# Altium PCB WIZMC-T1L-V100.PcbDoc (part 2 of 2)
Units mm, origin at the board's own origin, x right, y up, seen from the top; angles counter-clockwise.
Board outline 48.5 x 42.5 mm, 4 copper layers (Top Layer, GND, POWER, Bottom Layer), stack 0.603 mm thick; 133 components, 92 nets, 478 pads, 203 vias.
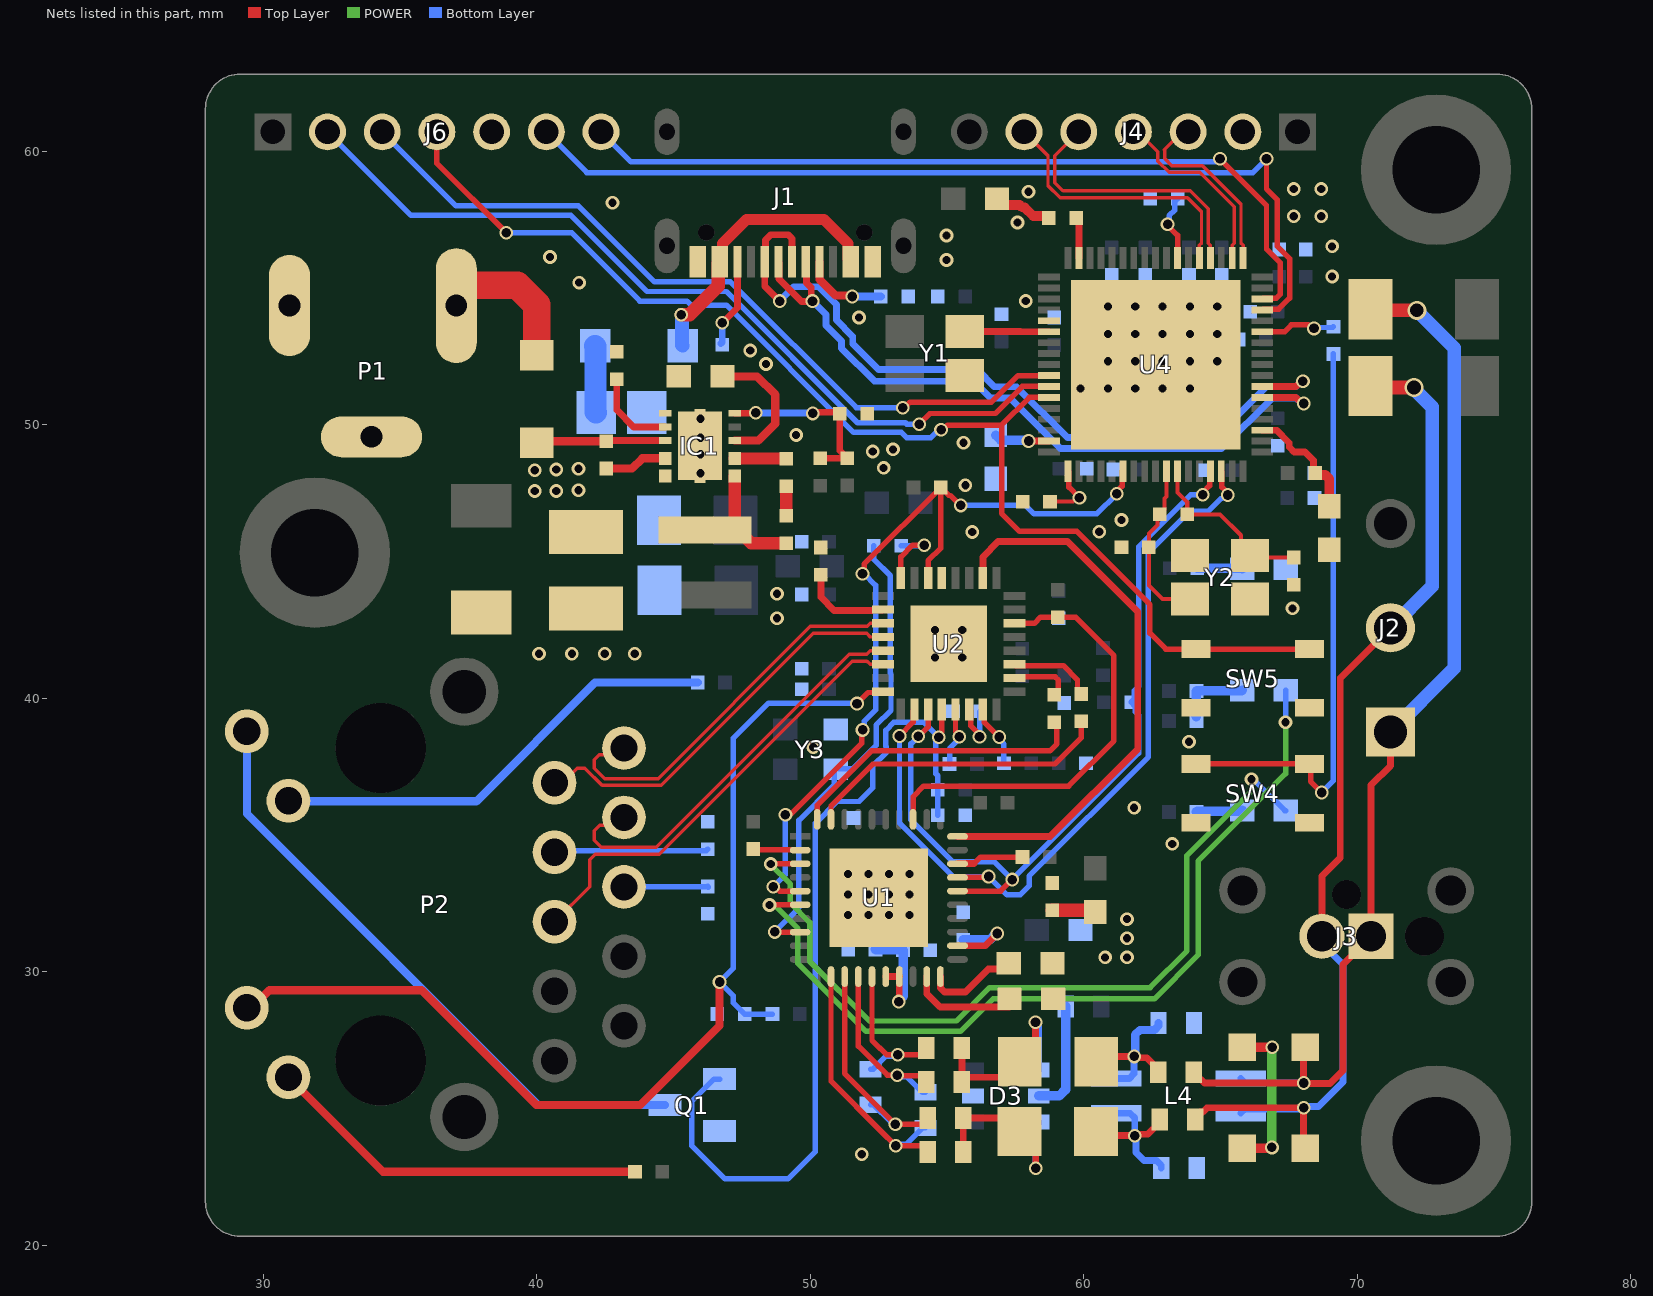
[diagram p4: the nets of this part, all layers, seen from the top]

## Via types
v1: diameter 0.5, hole 0.3, Top Layer to Bottom Layer, tented both sides, 116 vias
v2: diameter 0.5, hole 0.35, Top Layer to Bottom Layer, tented both sides, 81 vias
v3: diameter 0.6, hole 0.3, Top Layer to Bottom Layer, tented both sides, 4 vias
v4: diameter 0.7, hole 0.5, Top Layer to Bottom Layer, tented both sides, 2 vias

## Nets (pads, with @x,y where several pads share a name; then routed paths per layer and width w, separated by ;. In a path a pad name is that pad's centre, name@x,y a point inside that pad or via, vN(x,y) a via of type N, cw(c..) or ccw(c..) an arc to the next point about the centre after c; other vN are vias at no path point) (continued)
GND: C3.1 C4.1 C5.1 C6.1 C7.1 C8.1 C9.1 C10.1 C11.1 C12.1 C14.1 C15.1 C16.1 C17.1 C19.1 C20.2 C21.2 C22.1 C25.1 C29.1 C30.1 C31.1 C33.1 C34.1 C35.1 C36.1 C37.1 C38.1 C39.1 C40.1 C41.1 C43.2 C44.2 C45.1 C46.1 C47.1 C48.1 C49.1 C50.1 C51.1 C52.1 C53.1 C54.1 C55.1 C56.1 C57.1 D3.2 IC1.6 IC1.10 IC1.11 IC1.A11 IC1.B11 J1.A1_B12 J1.B1_A12 J4.2 J6.5 LD3.2 P1.2 P1.3 Q1.2 R3.1 R5.1 R10.2 R15.2 R16.1 R24.1 R33.1 R52.1 R53.1 R54.2 SW4.1 SW4.2 SW5.1 SW5.2 U1.41 U2.5 U2.33 U4.22 U4.69 Y1.2 Y2.2 Y2.4 Y3.2
  other v1: 51.877,23.32 51.377,32.07 52.127,32.07 52.877,32.07 53.627,32.07 51.377,32.82 52.127,32.82 52.877,32.82 53.627,32.82 51.377,33.57 52.127,33.57 52.877,33.57 53.627,33.57 63.234,34.671 61.837,35.992 50.102,38.202 63.843,38.405 40.077,41.62 41.277,41.62 42.477,41.62 43.577,41.62 48.777,42.92 67.628,43.282 48.777,43.82 55.917,46.076 60.558,46.086 61.372,46.513 55.667,47.783 45.977,48.22 52.677,48.42 45.977,48.92 52.277,49.02 53.018,49.096 55.599,49.34 45.977,49.52 49.477,49.62 45.977,50.22 59.877,51.32 60.877,51.32 61.877,51.32 62.877,51.32 63.877,51.32 48.373,52.216 60.877,52.32 61.877,52.32 62.877,52.32 63.877,52.32 64.877,52.32 47.8,52.714 60.877,53.32 61.877,53.32 62.877,53.32 63.877,53.32 64.877,53.32 51.777,53.92 60.877,54.32 61.877,54.32 62.877,54.32 63.877,54.32 64.877,54.32 57.877,54.52 41.542,55.194 69.077,55.42 54.977,56.02 40.475,56.134 69.077,56.52 54.977,56.92 57.569,57.396 67.677,57.62 68.677,57.62 42.761,58.115 57.977,58.52 67.677,58.62 68.677,58.62
  other v3: 54.555,41.486 55.555,41.486 54.555,42.486 55.555,42.486
LED0: P2.L2 R50.1 R53.2 U2.16 | length 40
  Top Layer w0.2: v2(51.702,39.802) 52.106,40.206 52.622,40.206 U2.16@52.652,40.236
  Top Layer w0.3: P2.L2@29.392,28.676 29.574,28.676 30.218,29.32 35.777,29.32 39.977,25.12 43.777,25.12 46.677,28.02 v2(46.677,29.62)
  Bottom Layer w0.2: R50.1@48.611,28.448 R53.2@47.597,28.448 47.177,28.868 47.177,29.12 v2(46.677,29.62) 47.177,30.12 47.177,38.528 48.469,39.82 51.684,39.82 v2(51.702,39.802)
LINK_ST: Q1.1 R49.1 R52.2 U2.20 | length 31.4
  Top Layer w0.2: v2@54.805,38.774 U2.20@54.805,39.584
  Bottom Layer w0.2: Q1.1@46.677,26.07 46.477,26.07 45.66,25.253 45.66,23.637 46.877,22.42 49.177,22.42 50.177,23.42 50.177,35.42 50.977,36.22 51.777,36.22 52.277,36.72 52.277,37.52 52.777,38.02 52.777,38.22 52.756,38.241 52.756,38.822 53.054,39.12 54.142,39.12 v2(54.687,38.575) 54.687,38.493 54.588,38.395 54.588,37.238 54.656,37.17 R49.1@54.656,36.652 R52.2@54.656,35.712
MDC: U1.27 U2.18 U4.49 | length 30.2
  Top Layer w0.2: v2(53.256,38.615) 53.256,38.622 53.755,39.121 53.755,39.534 U2.18@53.805,39.584 ; U1.27@55.377,33.444 55.385,33.452 56.488,33.452 v2(56.513,33.478) ; U4.49@65.024,48.297 65.049,48.272 65.049,47.72 65.259,47.51 v2(65.259,47.429)
  Bottom Layer w0.2: v2(53.256,38.615) 53.258,38.613 53.258,35.427 55.207,33.478 v2(56.513,33.478) 57.188,32.803 57.668,32.803 57.996,33.13 57.996,33.489 62.354,37.848 62.354,45.323 63.874,46.843 64.553,46.843 65.01,47.3 65.049,47.3 65.178,47.429 v2(65.259,47.429)
MDI_0_N: P2.R2 U2.12 | length 14.9
  Top Layer w0.125: P2.R2@40.642,36.906 40.932,36.906 41.466,37.44 41.747,37.44 42.378,36.809 44.541,36.809 50.104,42.371 52.052,42.371 52.187,42.236 U2.12@52.652,42.236
MDI_0_P: P2.R1 U2.11 | length 14.6
  Top Layer w0.125: P2.R1@43.182,38.176 42.928,37.922 42.279,37.922 42.101,37.744 42.101,37.44 42.482,37.059 44.438,37.059 50,42.621 52.072,42.621 52.187,42.736 U2.11@52.652,42.736
MDI_1_N: P2.R6 U2.14 | length 16.6
  Top Layer w0.125: P2.R6@40.642,31.826 41.923,33.107 41.923,34.087 42.13,34.294 44.465,34.294 51.526,41.355 52.068,41.355 52.187,41.236 U2.14@52.652,41.236
MDI_1_P: P2.R3 U2.13 | length 15.3
  Top Layer w0.125: P2.R3@43.182,35.636 42.9,35.354 42.301,35.354 42.101,35.154 42.101,34.798 42.355,34.544 44.361,34.544 51.423,41.605 52.056,41.605 52.187,41.736 U2.13@52.652,41.736
MDIO: R12.1 U1.26 U2.19 U4.48 | length 29.5
  Top Layer w0.2: v2(53.945,38.604) 53.959,38.604 54.305,38.95 U2.19@54.305,39.584 ; U1.26@55.377,32.944 56.956,32.944 v2(57.377,33.365) ; v2(64.351,47.438) 64.351,47.519 64.599,47.768 64.599,48.272 U4.48@64.624,48.297
  Bottom Layer w0.2: v2(53.945,38.604) 53.671,38.33 53.671,35.546 55.207,34.011 56.731,34.011 v2(57.377,33.365) 62.004,37.993 62.004,39.376 61.877,39.503 61.877,39.703 R12.1@61.727,39.853 61.841,39.966 61.841,40.263 62.004,40.427 62.004,45.532 63.91,47.438 v2(64.351,47.438)
MDIX_MODE: R46.1 U2.21 | length 2.2
  Top Layer w0.2: U2.21@55.305,39.584 55.305,38.796 55.437,38.664 v2(55.437,38.583)
  Bottom Layer w0.2: R46.1@55.088,37.592 55.088,38.153 55.437,38.502 v2(55.437,38.583)
MEDIA_CNV: R40.1 U1.2 | length 1.7
  Top Layer w0.2: R40.1@47.904,34.48 47.932,34.452 49.618,34.452 U1.2@49.626,34.444
NetC1_1: C1.1 R1.1 | length 1.1
  Top Layer w0.45: R1.1@49.116,46.668 C1.1@49.116,47.751
NetC1_2: C1.2 IC1.2 | length 1.9
  Top Layer w0.45: IC1.2@47.237,48.769 47.237,48.76 49.107,48.76 C1.2@49.116,48.751
NetC2_1: C2.1 IC1.5 R4.1 R5.2 | length 6.7
  Top Layer w0.25: IC1.5@47.237,50.419 47.983,50.419 v2(47.999,50.435) ; v2(50.081,50.41) 50.124,50.452 51.03,50.452 51.072,50.494 51.072,49.054 R4.1@51.35,48.776 51.346,48.772 50.363,48.772 C2.1@50.359,48.768
  Bottom Layer w0.25: v2(47.999,50.435) 48.011,50.423 50.069,50.423 v2(50.081,50.41)
NetC18_1: C18.1 D3.4 R7.2 R9.2 | length 7.1
  Top Layer w0.25: R7.2@55.539,27.208 R9.2@55.539,25.963 55.713,26.137 57.092,26.137 C18.1@57.655,26.7 58.23,27.275 v2(58.23,28.143)
  Bottom Layer w0.25: v2(58.23,28.143) 58.23,28.076 58.35,27.955 D3.4@58.35,26.405
NetC18_2: C18.2 L4.2 R8.2 R10.1 | length 5.9
  Top Layer w0.25: C18.2@60.455,26.7 60.654,26.899 v2(61.837,26.899) 61.884,26.851 62.291,26.851 62.723,26.419 R8.2@62.723,26.319
  Bottom Layer w0.25: L4.2@61.185,26.09 61.662,26.09 61.837,26.265 v2(61.837,26.899)
  Bottom Layer w0.3: v2(61.837,26.899) 61.875,26.937 61.875,27.694 62.051,27.87 62.577,27.87 62.727,28.02 R10.1@62.727,28.12
NetC22_2: C22.2 IC1.3 | length 5
  Top Layer w0.3: C22.2@46.787,51.765 48.047,51.765 48.716,51.096 48.716,50.035 48.1,49.419 IC1.3@47.237,49.419
NetC23_2: C23.2 D4.1 J2.2 J3.2 L4.4 R36.1 | length 39.1
  Top Layer w0.25: R36.1@64.074,24.592 64.074,24.692 64.249,24.867 64.349,24.867 64.501,25.019 v2(68.034,25.019) 68.034,23.604 D4.1@68.092,23.546 ; J3.2@68.704,31.293 68.704,33.493 69.377,34.166 69.377,40.738 J2.2@71.209,42.57
  Top Layer w0.5: C23.2@70.478,51.41 70.529,51.359 v4(72.073,51.359)
  Bottom Layer w0.25: L4.4@65.735,24.82 65.886,24.971 v2@67.986,24.971 ; v2(68.034,25.019) 68.082,25.067 68.575,25.067 69.472,25.964 69.472,30.254 68.704,31.021 J3.2@68.704,31.293
  Bottom Layer w0.5: J2.2@71.209,42.57 72.733,44.094 72.733,50.644 72.073,51.305 v4(72.073,51.359)
NetC24_2: C24.2 D2.2 J2.1 J3.1 L4.3 R8.1 | length 41.3
  Top Layer w0.25: R8.1@64.023,26.319 64.023,26.219 64.198,26.044 64.298,26.044 64.415,25.926 v2(68.038,25.926) ; D2.2@68.092,27.229 68.034,27.171 68.034,25.93 v2(68.038,25.926) ; J2.1@71.209,38.76 71.209,37.525 70.504,36.82 J3.1@70.504,31.293 69.472,30.261 69.472,26.38 68.999,25.908 68.056,25.908 v2(68.038,25.926)
  Top Layer w0.5: C24.2@70.478,54.218 70.519,54.178 v4(72.174,54.178)
  Bottom Layer w0.25: L4.3@65.735,26.09 65.892,25.933 68.031,25.933 v2(68.038,25.926)
  Bottom Layer w0.5: J2.1@71.209,38.76 73.546,41.097 73.546,52.807 v4(72.174,54.178)
NetC25_2: C25.2 R13.1 U4.54 | length 4.5
  Top Layer w0.25: U4.54@66.524,49.797 67.038,49.797 67.509,49.326 67.509,49.183 67.691,49.002 68.087,49.002 68.391,48.698 68.391,48.302 R13.1@68.458,48.235
  Top Layer w0.35: R13.1@68.458,48.235 68.533,48.16 68.832,48.16 68.977,48.015 C25.2@68.977,47.02
NetC33_2: C33.2 U4.35 | length 2.3
  Top Layer w0.15: C33.2@58.763,47.187 59.604,47.187 59.743,47.326 v2(59.837,47.326)
  Top Layer w0.2: U4.35@59.424,48.297 59.449,48.272 59.449,47.715 59.837,47.327 v2(59.837,47.326)
NetC38_2: C38.2 U4.33 | length 2
  Top Layer w0.2: U4.33@58.721,49.4 U4.33@58.724,49.397
  Top Layer w0.25: v2(57.976,49.403) 57.979,49.4 U4.33@58.721,49.4
  Bottom Layer w0.35: C38.2@56.777,49.62 56.965,49.432 57.947,49.432 v2(57.976,49.403)
NetC42_1: C42.1 D3.6 R35.2 R37.2 | length 6.8
  Top Layer w0.25: R37.2@55.59,23.398 R35.2@55.59,24.642 57.156,24.642 58.238,23.56 v2(58.238,22.811)
  Bottom Layer w0.25: v2(58.238,22.811) 58.238,24.393 D3.6@58.35,24.505
NetC42_2: C42.2 L4.1 R33.2 R36.2 | length 5.9
  Top Layer w0.25: C42.2@60.443,24.155 60.595,24.003 v2(61.862,24.003) 61.91,24.051 62.333,24.051 62.774,24.492 R36.2@62.774,24.592
  Bottom Layer w0.25: L4.1@61.185,24.82 61.687,24.82 61.862,24.645 v2(61.862,24.003) 61.91,23.955 61.91,23.387 62.202,23.095 62.652,23.095 62.827,22.92 R33.2@62.827,22.82
NetC43_1: C43.1 U1.19 | length 3.9
  Top Layer w0.25: U1.19@54.252,29.819 54.252,29.197 54.747,28.702 C43.1@57.277,28.702
NetC44_1: C44.1 U1.20 | length 3.3
  Top Layer w0.25: U1.20@54.752,29.819 54.756,29.815 54.756,29.405 54.902,29.259 55.665,29.259 56.505,30.099 C44.1@57.252,30.099
NetC54_2: C54.2 U2.22 | length 2.1
  Top Layer w0.2: U2.22@55.805,39.584 55.855,39.534 55.855,38.992 56.183,38.664 v2(56.183,38.583)
  Bottom Layer w0.2: v2(56.183,38.583) 56.199,38.599 56.199,39.506 C54.2@56.215,39.522
NetC55_2: C55.2 P2.R4 | length 5.6
  Bottom Layer w0.2: P2.R4@40.642,34.366 40.697,34.421 46.186,34.421 C55.2@46.241,34.476
NetC56_2: C56.2 P2.R5 | length 3.1
  Top Layer w0.2: P2.R5@43.182,33.096 P2.R5@43.204,33.118
  Bottom Layer w0.2: P2.R5@43.182,33.096 43.191,33.105 46.232,33.105 C56.2@46.241,33.114 C56.2@46.262,33.092
NetD1_2: D1.2 P1.1 | length 5.2
  Top Layer w1: P1.1@37.035,55.296 37.239,55.092 39.285,55.092 39.998,54.38 D1.2@39.998,52.543
NetD2_1: D2.1 D4.2 | length 5.9
  Top Layer w0.25: D4.2@65.792,23.546 D4.2@65.817,23.571
  Top Layer w0.35: D4.2@65.792,23.546 66.877,23.546 v2(66.877,23.57) ; D2.1@65.792,27.229 v2(66.891,27.229)
  POWER w0.35: v2(66.877,23.57) 66.877,27.229 v2(66.891,27.229)
NetD3_5: D3.5 R6.2 | length 4.1
  Bottom Layer w0.35: D3.5@58.35,25.455 59.098,25.455 59.332,25.69 R6.2@59.332,28.727
NetD5_2: D5.2 J1.A4_B9 J1.B4_A9 | length 10.6
  Top Layer w0.4: J1.B4_A9@46.679,55.956 46.779,56.056 46.779,56.621 47.663,57.506 50.494,57.506 51.379,56.621 51.379,56.056 J1.A4_B9@51.479,55.956
  Top Layer w0.5: v2(45.277,54.02) 45.577,54.02 46.629,55.072 46.629,55.906 J1.B4_A9@46.679,55.956
  Bottom Layer w0.5: v2(45.277,54.02) 45.301,53.996 45.301,52.908 D5.2@45.326,52.883
NetIC1_1: IC1.1 L1.1 R1.2 | length 6.2
  Top Layer w0.45: IC1.1@47.237,48.119 47.237,46.143 L1.1@46.139,46.143 47.349,46.143 47.824,45.668 R1.2@49.116,45.668
NetIC1_7: IC1.7 R3.2 | length 3.1
  Top Layer w0.25: R3.2@42.919,51.662 42.919,50.537 43.536,49.919 IC1.7@44.687,49.919
NetIC1_9: IC1.9 R2.2 | length 2.4
  Top Layer w0.3: R2.2@42.576,48.352 R2.2@42.533,48.395 43.479,48.395 43.853,48.769 IC1.9@44.687,48.769 IC1.9@44.643,48.726
NetJ1_A5: J1.A5 R15.1 | length 3.1
  Top Layer w0.3: J1.A5@50.329,55.956 50.329,55.312 50.916,54.724 51.486,54.724 v2(51.524,54.686)
  Bottom Layer w0.3: v2(51.524,54.686) R15.1@52.574,54.686
NetJ1_B5: J1.B5 R16.2 | length 3.2
  Top Layer w0.25: v2(46.775,53.722) 47.329,54.275 J1.B5@47.329,55.956
  Bottom Layer w0.25: R16.2@46.723,52.974 46.776,53.027 v2@46.776,53.721
NetLD1_2: LD1.2 R29.2 | length 2.1
  Top Layer w0.35: LD1.2@56.884,58.268 56.884,58.239 57.09,58.033 57.651,58.033 57.739,57.945 57.833,57.945 58.147,57.631 58.645,57.631 R29.2@58.72,57.556
NetLD3_1: LD3.1 R31.2 | length 1.7
  Bottom Layer w0.35: R31.2@64.14,44.755 64.153,44.742 65.774,44.742 LD3.1@65.786,44.729
NetLD4_1: LD4.1 R41.1 | length 1.7
  Bottom Layer w0.35: R41.1@64.115,35.839 64.14,35.865 65.76,35.865 LD4.1@65.785,35.89
NetLD4_2: LD4.2 U1.3 | length 30
  Top Layer w0.2: v1(48.552,33.934) 48.557,33.939 49.621,33.939 U1.3@49.626,33.944
  POWER w0.2: v1@48.54,33.922 49.264,33.198 49.264,32.512 49.975,31.801 49.975,30.378 52.159,28.194 55.334,28.194 56.553,29.413 62.421,29.413 63.767,30.759 63.767,34.239 66.129,36.601 v1(66.129,37.033)
  Bottom Layer w0.2: v1(66.129,37.033) 66.207,37.033 67.35,35.89 LD4.2@67.385,35.89
NetLD5_1: LD5.1 R38.1 R42.1 | length 2.6
  Bottom Layer w0.35: R38.1@64.115,39.319 R42.1@64.115,40.259 64.127,40.272 65.772,40.272 LD5.1@65.785,40.284
NetLD5_2: LD5.2 U1.6 | length 31.6
  Top Layer w0.2: v1(48.502,32.436) 48.506,32.44 49.622,32.44 U1.6@49.626,32.444
  POWER w0.2: v1(48.502,32.436) 48.559,32.378 48.737,32.378 49.543,31.572 49.543,30.302 52.032,27.813 55.487,27.813 56.68,29.007 62.573,29.007 64.178,30.612 64.178,34.041 67.374,37.236 v1(67.374,39.116)
  Bottom Layer w0.2: v1(67.374,39.116) 67.374,40.273 LD5.2@67.385,40.284
NetP2_L1: P2.L1 R58.1 | length 14.1
  Top Layer w0.3: P2.L1@30.912,26.136 34.366,22.682 R58.1@43.582,22.682
NetP2_L3: P2.L3 R34.1 | length 16.8
  Bottom Layer w0.3: P2.L3@30.912,36.246 30.932,36.226 37.783,36.226 42.127,40.57 R34.1@45.877,40.57
NetP2_L4: P2.L4 Q1.3 | length 22.7
  Bottom Layer w0.3: P2.L4@29.392,38.786 29.392,35.772 40.044,25.12 Q1.3@44.677,25.12
NetR14_1: R14.1 U4.63 | length 2.8
  Top Layer w0.2: U4.63@66.524,53.397 67.337,53.397 67.586,53.646 68.206,53.646 68.333,53.519 v2(68.414,53.519)
  Bottom Layer w0.2: v2(68.414,53.519) 68.448,53.553 69.093,53.553 R14.1@69.126,53.586
NetR24_2: R24.2 U4.7 | length 2.5
  Top Layer w0.2: v2(63.059,57.331) 63.059,57.283 63.424,56.918 U4.7@63.424,56.097 U4.7@63.43,56.103
  Bottom Layer w0.2: v2(63.059,57.331) 63.116,57.388 63.116,57.642 63.323,57.849 63.323,58.162 R24.2@63.429,58.268
NetR54_1: R54.1 U2.10 | length 3.3
  Top Layer w0.25: R54.1@50.381,44.509 50.381,43.691 50.862,43.21 52.251,43.21 52.252,43.211 52.627,43.211 U2.10@52.652,43.236
NetR55_1: R55.1 U2.27 | length 3.1
  Top Layer w0.2: U2.27@57.457,41.236 57.506,41.187 59.249,41.187 59.766,40.67 59.766,40.289 R55.1@59.906,40.149
NetR56_1: R56.1 U2.26 | length 2.3
  Top Layer w0.2: U2.26@57.457,40.736 57.5,40.779 58.946,40.779 59.063,40.662 59.063,40.271 R56.1@58.916,40.124
NetR57_1: R57.1 U2.8 | length 2.7
  Top Layer w0.2: U2.8@53.305,44.389 53.305,45.164 53.734,45.593 v2(54.166,45.593)
  Bottom Layer w0.2: R57.1@53.32,45.568 53.332,45.58 54.153,45.58 v2(54.166,45.593)
PHY_RESET_N: R51.2 U1.5 U2.6 U4.40 | length 30.3
  Top Layer w0.2: v2(48.641,33.101) 48.722,33.101 48.879,32.944 U1.5@49.626,32.944 ; v2(49.086,35.738) 49.143,35.795 49.321,35.795 51.872,38.346 51.872,38.803 v2(51.906,38.837) ; v2(51.905,44.552) 51.963,44.609 51.963,44.896 R51.2@54.767,47.701 ; U2.6@54.305,44.389 54.305,45.025 54.767,45.487 R51.2@54.767,47.701 ; v2(55.498,47.047) 55.48,47.047 55.117,47.41 55.059,47.41 R51.2@54.767,47.701 ; v2(61.202,47.473) 61.202,47.554 61.399,47.751 61.399,48.272 U4.40@61.424,48.297
  Bottom Layer w0.2: v2(48.641,33.101) 48.641,33.104 49.086,33.548 v2(49.086,35.738) ; v2(51.905,44.552) 51.956,44.552 52.388,44.12 52.388,39.573 51.963,39.149 51.963,38.894 v2(51.906,38.837) ; v2(55.498,47.047) 57.867,47.047 58.178,46.736 60.465,46.736 v2(61.202,47.473)
PHYAD_1: R39.1 U1.28 | length 2.5
  Top Layer w0.2: 55.983,33.948 56.223,34.188 R39.1@57.755,34.188
  Top Layer w0.25: U1.28@55.377,33.944 55.381,33.948 55.983,33.948
PHYAD_3: R45.1 U2.23 | length 2.3
  Top Layer w0.2: U2.23@56.305,39.584 56.355,39.534 56.355,39.123 v2(56.9,38.578)
  Bottom Layer w0.2: v2@56.94,38.538 v2(56.9,38.578) 56.9,38.497 57.077,38.32 R45.1@57.077,37.62
R_N: J4.5 U4.4 | length 10.1
  Top Layer w0.125: J4.5@59.811,60.706 58.936,59.831 58.936,58.845 59.234,58.547 63.892,58.547 64.55,57.889 64.55,56.633 64.624,56.559 U4.4@64.624,56.097
R_P: J4.6 U4.5 | length 10.1
  Top Layer w0.125: J4.6@57.811,60.706 58.686,59.831 58.686,58.742 59.131,58.297 63.788,58.297 64.3,57.785 64.3,56.636 64.224,56.559 U4.5@64.224,56.097
RP_BOOT: R14.2 SW4.3 SW4.4 | length 21.6
  Top Layer w0.2: SW4.4@64.102,37.595 SW4.3@68.252,37.595 68.288,37.559 68.288,36.957 v2(68.695,36.551)
  Bottom Layer w0.2: v2(68.695,36.551) 69.126,36.982 R14.2@69.126,52.586
RSTn: J6.4 SW5.3 SW5.4 U4.29 | length 45.5
  Top Layer w0.2: J6.4@36.342,60.706 36.342,59.555 v2(38.877,57.02) ; v2(54.777,49.82) 54.858,49.82 55.02,49.982 56.991,49.982 ; U4.29@58.724,50.997 58.007,50.997 56.991,49.982 ; SW5.3@68.252,41.795 SW5.4@64.102,41.795 62.996,41.795 62.416,42.375 62.416,43.421 59.739,46.098 57.653,46.098 56.991,46.76 56.991,49.982
  Bottom Layer w0.2: v2(38.877,57.02) 41.265,57.02 43.765,54.52 45.484,54.52 45.632,54.371 46.925,54.371 51.577,49.72 53.327,49.72 53.527,49.52 54.396,49.52 54.696,49.82 v2(54.777,49.82)
STATUS_LED0: R29.1 U4.16 | length 1.5
  Top Layer w0.25: R29.1@59.72,57.556 59.824,57.453 U4.16@59.824,56.097
SWCLK: J6.3 U4.27 | length 29
  Top Layer w0.2: v2(53.377,50.62) 53.444,50.62 53.644,50.82 56.62,50.82 57.597,51.797 U4.27@58.724,51.797
  Bottom Layer w0.2: J6.3@34.342,60.706 37.045,58.003 41.515,58.003 44.298,55.22 47.077,55.22 51.677,50.62 v2(53.377,50.62)
SWDIO: J6.2 U4.28 | length 31.4
  Top Layer w0.2: v2(53.977,50.02) 54.365,50.408 56.765,50.408 57.754,51.397 U4.28@58.724,51.397
  Bottom Layer w0.2: J6.2@32.342,60.706 35.395,57.653 41.244,57.653 44.027,54.87 46.927,54.87 51.727,50.07 53.472,50.07 53.522,50.02 v2(53.977,50.02)
SWPD_ENB: R44.1 U1.33 U2.30 | length 16.5
  Top Layer w0.2: U1.33@53.752,35.57 53.752,36.391 54.14,36.779 59.445,36.779 61.1,38.435 61.1,41.554 59.695,42.959 R44.1@59.043,42.959 58.413,42.959 58.19,42.736 U2.30@57.457,42.736
T1L_AVDD_3V3: C37.2 C39.2 C40.2 C41.2 L3.2 U1.16 U1.17 U1.22 | length 9
  Top Layer w0.25: U1.16@52.752,29.819 U1.17@53.252,29.819 53.248,29.815 53.248,28.927 v2(53.226,28.905) ; U1.22@55.377,30.944 56.383,30.944 v2(56.833,31.394)
  Top Layer w0.35: C37.2@58.839,32.241 C37.2@58.869,32.211
  Top Layer w0.5: C37.2@58.839,32.241 60.356,32.241 L3.2@60.414,32.182
  Bottom Layer w0.35: C39.2@52.38,30.81 52.392,30.797 53.374,30.797 C41.2@53.386,30.785 53.386,29.106 53.226,28.946 v2(53.226,28.905) ; C40.2@55.588,31.166 56.564,31.166 56.792,31.394 v2(56.833,31.394)
  other v1: 60.777,30.52 61.577,30.52 61.577,31.22 61.577,31.92
T1L_RXD1: U1.30 U2.2 | length 20.7
  Top Layer w0.25: U1.30@55.377,34.944 58.768,34.944 61.972,38.148 61.972,43.146 59.395,45.723 56.862,45.723 56.305,45.167 U2.2@56.305,44.389
T1L_RXN: R32.1 R35.1 U1.13 | length 8.7
  Top Layer w0.2: U1.13@51.252,29.819 51.252,26.274 v2(53.109,24.417) 54.09,24.417 54.29,24.617 R35.1@54.29,24.642
  Bottom Layer w0.2: R32.1@52.197,25.135 52.297,25.135 52.958,24.474 53.051,24.474 v2(53.109,24.417)
T1L_RXP: R9.1 R11.2 U1.14 | length 6.9
  Top Layer w0.2: U1.14@51.752,29.819 51.752,27.276 52.481,26.547 52.81,26.218 v2@53.176,26.218 ; v2(53.176,26.207) 53.191,26.192 54.039,26.192 54.239,25.992 R9.1@54.239,25.963
  Bottom Layer w0.2: v2(53.176,26.207) 53.233,26.149 53.536,26.149 54.104,25.582 R11.2@54.204,25.582
T1L_TXD0: R55.2 U1.39 | length 11.3
  Top Layer w0.2: U1.39@50.752,35.57 50.752,36.058 52.286,37.592 58.941,37.592 59.906,38.557 R55.2@59.906,39.149
T1L_TXD1: R56.2 U1.40 | length 11
  Top Layer w0.2: U1.40@50.252,35.57 50.252,36.091 52.235,38.075 58.757,38.075 59.012,38.329 59.012,39.027 R56.2@58.916,39.124
T1L_TXN: R11.1 R37.1 U1.12 | length 9.8
  Top Layer w0.2: U1.12@50.752,29.819 50.752,25.997 52.571,24.178 v2(53.115,23.634) 54.09,23.634 54.29,23.434 R37.1@54.29,23.398
  Bottom Layer w0.2: v2(53.115,23.634) 53.173,23.691 53.512,23.691 54.104,24.282 R11.1@54.204,24.282
T1L_TXP: R7.1 R32.2 U1.15 | length 5.9
  Top Layer w0.2: U1.15@52.252,29.819 52.252,27.483 52.54,27.195 52.554,27.195 52.787,26.963 v2(53.19,26.963) 54.039,26.963 54.239,27.163 R7.1@54.239,27.208
  Bottom Layer w0.2: R32.2@52.197,26.435 52.297,26.435 52.767,26.906 53.132,26.906 v2(53.19,26.963)
T_N: J4.3 U4.1 | length 6.9
  Top Layer w0.125: J4.3@63.811,60.706 63.597,60.706 62.936,60.046 62.958,60.024 62.958,59.733 63.217,59.474 64.336,59.474 65.744,58.066 65.744,56.639 65.824,56.559 U4.1@65.824,56.097
T_P: J4.4 U4.2 | length 6.9
  Top Layer w0.125: J4.4@61.811,60.706 61.974,60.706 62.708,59.972 62.708,59.63 63.113,59.224 64.233,59.224 65.494,57.963 65.494,56.63 65.424,56.559 U4.2@65.424,56.097
U_RXD0: J6.7 U4.66 | length 29.7
  Top Layer w0.2: v2(64.977,59.72) 66.677,58.02 66.677,56.42 67.174,55.923 67.174,54.768 67.028,54.622 66.549,54.622 U4.66@66.524,54.597
  Bottom Layer w0.2: J6.7@42.342,60.706 43.442,59.606 64.782,59.606 64.896,59.72 v2(64.977,59.72)
U_TXD0: J6.6 U4.65 | length 33.8
  Top Layer w0.2: U4.65@66.524,54.197 66.549,54.222 67.123,54.222 67.524,54.623 67.524,56.073 67.077,56.52 67.077,58.22 66.677,58.62 v2(66.677,59.72)
  Bottom Layer w0.2: J6.6@40.342,60.706 41.828,59.22 66.177,59.22 v2(66.677,59.72)
USB_N: J1.A7 J1.B7 U4.57 | length 26.8
  Top Layer w0.25: J1.A7@48.829,55.956 48.854,55.931 48.854,55.322 49.674,54.501 50.058,54.501 v2(50.077,54.52) 50.029,54.568 50.029,55.011 49.854,55.186 49.854,55.931 J1.B7@49.829,55.956 ; U4.57@66.524,50.997 67.759,50.997 67.982,50.775 v2(68.034,50.775)
  Bottom Layer w0.25: v2(50.077,54.52) 50.572,54.024 50.572,53.628 51.14,53.06 51.14,52.794 52.345,51.589 55.966,51.589 56.577,50.978 57.29,50.978 59.144,49.124 65.037,49.124 66.891,50.978 67.763,50.978 67.967,50.775 v2(68.034,50.775)
USB_P: J1.A6 J1.B6 U4.58 | length 29
  Top Layer w0.25: v2(48.877,54.52) 48.329,55.068 J1.B6@48.329,55.956 48.354,55.981 48.354,56.748 48.552,56.947 49.182,56.947 49.329,56.8 J1.A6@49.329,55.956 ; U4.58@66.524,51.397 67.038,51.397 67.039,51.396 67.75,51.396 67.941,51.587 v2(68.009,51.587)
  Bottom Layer w0.25: v2(48.877,54.52) 49.402,55.045 50.294,55.045 50.947,54.392 50.947,53.828 51.547,53.228 51.547,52.962 52.489,52.02 56.101,52.02 56.737,51.384 57.544,51.384 59.398,49.53 64.808,49.53 66.663,51.384 67.738,51.384 67.941,51.587 v2(68.009,51.587)
VBUS: C19.2 C31.2 D1.1 D5.1 IC1.8 R2.1 | length 7.9
  Top Layer w0.25: R2.1@42.533,49.395 42.557,49.419 IC1.8@44.687,49.419
  Top Layer w0.3: D1.1@39.998,49.343 40.049,49.395 R2.1@42.533,49.395 ; C19.2@41.293,45.576 C19.2@41.796,46.079
  Bottom Layer w0.8: D5.1@42.126,52.883 42.146,52.863 42.146,50.464 C31.2@42.166,50.444
  other v1: 39.916,47.574 40.704,47.574 41.517,47.6 39.916,48.336 40.704,48.362 41.517,48.387
XIN: U4.23 Y1.3 | length 2.4
  Top Layer w0.25: Y1.3@56.333,53.403 57.675,53.403 57.682,53.397 U4.23@58.724,53.397
XTAL1: C29.2 R21.1 U4.45 Y2.1 | length 6.6
  Top Layer w0.15: U4.45@63.424,48.297 63.424,47.521 63.778,47.167 63.778,46.721 R21.1@63.777,46.72 64.977,46.72 65.74,45.957 65.74,45.745 66.065,45.42 Y2.1@66.377,45.42 ; Y2.1@66.077,45.22 66.152,45.145 C29.2@67.675,45.145
XTAL2: C30.2 R21.2 U4.44 Y2.3 | length 6.2
  Top Layer w0.15: U4.44@63.024,48.297 63.024,47.367 62.952,47.295 62.952,46.895 62.691,46.634 62.691,46.333 62.377,46.019 C30.2@62.377,45.52 62.377,44.12 62.877,43.62 Y2.3@63.877,43.62
XTAL_IN: R57.2 U1.8 Y3.3 | length 17.4
  Top Layer w0.2: v2(48.692,31.45) 48.695,31.447 49.624,31.447 U1.8@49.626,31.444
  Bottom Layer w0.2: v2(48.692,31.45) 49.577,32.335 49.577,35.531 50.863,36.818 50.863,37.338 50.947,37.423 51.558,37.423 52.406,38.27 52.406,39.013 52.947,39.554 52.947,40.896 52.921,40.921 52.921,44.475 52.32,45.077 R57.2@52.32,45.568
pads on no net: D3.1 D3.3 IC1.4 J1. J1.A8 J1.B8 J3. P2.0 P2.R8 P2.R9 P2.R10 U1.1 U1.4 U1.7 U1.9 U1.10 U1.11 U1.18 U1.21 U1.25 U1.29 U1.32 U1.34 U1.36 U1.38 U2.3 U2.4 U2.7 U2.17 U2.24 U2.31 U4.9 U4.10 U4.11 U4.12 U4.14 U4.15 U4.17 U4.18 U4.19 U4.20 U4.21 U4.24 U4.30 U4.32 U4.36 U4.37 U4.38 U4.39 U4.41 U4.46 U4.47 U4.67 U4.68 Y1.1

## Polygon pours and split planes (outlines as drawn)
GND on Top Layer "GND" (solid, pour order 128): 27.877,62.82 76.377,62.82 76.377,20.32 27.877,20.32
CH_GND on Top Layer "CH_GND" (solid, pour order 102): 35.377,44.36 35.377,41.636 37.527,41.636 cw(c37.527,40.421) 38.742,40.421 38.742,40.052 cw(c37.579,40.052) 37.579,38.888 28.127,38.888 28.127,44.32
CH_GND on Top Layer "CH_GND" (solid, pour order 99): 28.127,48.82 39.153,48.82 39.153,46.07 35.377,46.07 35.377,44.61 cw(c32.837,44.61) 32.837,42.07 28.127,42.07
CH_GND on Top Layer "CH_GND" (solid, pour order 95): 67.127,62.32 67.127,60.07 69.877,60.07 69.877,62.32
CH_GND on Top Layer "CH_GND" (solid, pour order 98): 76.127,27.32 71.917,27.32 ccw(c71.917,24.78) 69.377,24.78 69.377,20.57 76.127,20.57
CH_GND on Top Layer "CH_GND" (solid, pour order 107): 69.377,62.57 69.377,58.61 ccw(c71.917,58.61) 71.917,56.07 72.627,56.07 cw(c72.627,55.57) 73.127,55.57 73.127,20.32 76.127,20.32 76.127,62.57
3V3 on Top Layer "3V3" (solid, pour order 115): 44.377,44.32 48.127,44.32 48.127,41.82 47.627,41.82 47.627,41.32 44.377,41.32
T1L_AVDD_3V3 on Top Layer "T1L_AVDD_3V3" (solid, pour order 127): 59.977,32.62 62.077,32.62 62.077,30.12 59.977,30.12
3V3 on Top Layer "3V3" (solid, pour order 125): 57.121,40.378 57.121,39.292 58.351,39.292 58.351,40.378
3V3 on Top Layer "3V3" (solid, pour order 124): 59.977,35.52 59.977,33.32 62.077,33.32 62.077,35.52
3V3 on Top Layer "3V3" (solid, pour order 123): 66.129,49.53 66.129,48.743 65.291,48.743 65.291,47.879 65.697,47.879 65.697,47.066 67.729,47.066 67.729,48.666 66.917,48.666 66.917,49.53
3V3 on Top Layer "3V3" (solid, pour order 119): 49.695,48.07 51.877,48.07 51.877,46.259 49.695,46.259
VBUS on Top Layer "GND" (solid, pour order 114): 39.383,49.911 42.837,49.911 43.218,49.53 43.218,45.11 39.662,45.11 39.662,48.438 39.383,48.438
NetIC1_1 on Top Layer "NetIC1_1" (solid, pour order 111): 47.003,48.362 47.003,47.701 46.495,47.193 44.387,47.193 44.387,45.542 49.391,45.542 49.391,46.025 48.527,46.025 47.511,47.041 cw(c47.556,47.086) 47.492,47.086 47.492,48.358
GND on Bottom Layer "GND" (solid, pour order 129): 27.877,62.82 27.877,20.32 76.377,20.32 76.377,62.82
CH_GND on Bottom Layer "CH_GND" (solid, pour order 96): 69.377,62.57 69.377,58.36 ccw(c71.917,58.36) 71.917,55.82 72.877,55.82 cw(c72.877,55.07) 73.627,55.07 73.627,35.068 cw(c72.525,35.07) 72.525,33.968 65.925,33.968 ccw(c65.925,32.836) 64.794,32.836 64.794,29.749 ccw(c65.925,29.749) 65.925,28.618 71.329,28.618 cw(c71.329,27.82) 72.127,27.82 71.917,27.82 ccw(c71.917,25.28) 69.377,25.28 69.377,23.82 cw(c67.877,23.82) 67.877,22.32 41.377,22.32 cw(c41.377,24.82) 38.877,24.82 ccw(c37.377,24.82) 37.377,26.32 37.127,26.32 ccw(c37.127,24.82) 35.627,24.82 35.627,20.57 76.127,20.57 76.127,62.57
3V3 on Bottom Layer "3V3" (solid, pour order 101): 46.377,47.57 46.377,42.657 44.377,42.657 44.377,41.3 46.468,41.3 46.468,40.309 47.127,40.309 47.127,41.32 48.127,41.32 48.127,47.57
3V3 on Bottom Layer "3V3" (solid, pour order 118): 57.077,41.02 57.077,39.12 58.377,39.12 58.377,41.02
3V3A on Bottom Layer "3V3A" (solid, pour order 112): 53.48,46.66 53.48,47.65 53.48,49.124 55.614,49.124 55.614,48.235 54.623,48.235 54.623,46.66
3V3 on Bottom Layer "3V3" (solid, pour order 103): 46.377,47.82 52.877,47.82 52.877,46.32 46.377,46.32
VBUS on Bottom Layer "VBUS" (solid, pour order 100): 41.263,53.569 41.263,48.997 39.485,48.997 39.485,47.117 42.787,47.117 42.787,53.569
T1L_AVDD_3V3 on POWER "T1L_AVDD_3V3" (solid, pour order 116): 62.077,32.62 58.377,32.62 57.477,31.72 55.577,31.72 52.877,29.02 52.877,28.62 53.577,28.62 55.877,30.92 59.877,30.92 59.877,30.12 62.077,30.12
3V3 on POWER "3V3" (solid, pour order 108): 44.377,42.82 44.377,41.326 48.121,41.326 48.121,42.824
3V3 on POWER "3V3" (solid, pour order 113): 57.077,40.22 57.077,39.12 58.677,39.12 58.677,40.22
3V3 on POWER "3V3" (solid, pour order 110): 59.977,35.52 59.977,34.32 62.077,34.32 62.077,35.52
3V3 on POWER "3V3" (solid, pour order 106): 49.213,46.304 51.877,46.304 51.877,51.57 51.627,51.82 50.627,50.82 50.627,49.57 49.213,48.156
3V3A on POWER "3V3A" (solid, pour order 105): 53.479,49.129 53.479,48.251 55.627,48.251 55.627,49.129
3V3A on POWER "3V3A" (solid, pour order 104): 54.877,49.07 58.627,52.82 58.627,55.07 60.377,56.82 65.377,56.82 65.377,55.82 61.127,55.82 60.127,54.82 60.127,52.57 55.807,48.251 54.877,48.251
GND on GND "GND" (solid, pour order 121): 27.877,62.82 76.377,62.82 76.377,20.32 27.877,20.32
CH_GND on GND "CH_GND" (solid, pour order 120): 69.377,62.57 69.377,58.36 ccw(c71.917,58.36) 71.917,55.82 72.877,55.82 cw(c72.877,55.07) 73.627,55.07 73.627,35.07 cw(c72.525,35.07) 72.525,33.968 65.925,33.968 ccw(c65.925,32.836) 64.794,32.836 64.794,29.749 ccw(c65.925,29.749) 65.925,28.618 71.329,28.618 cw(c71.329,27.82) 72.127,27.82 71.917,27.82 ccw(c71.917,25.28) 69.377,25.28 69.377,23.82 cw(c67.877,23.82) 67.877,22.32 41.377,22.32 cw(c41.377,24.82) 38.877,24.82 ccw(c37.377,24.82) 37.377,26.32 37.127,26.32 ccw(c37.127,24.82) 35.627,24.82 35.627,20.57 76.127,20.57 76.127,62.57

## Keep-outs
Keep-Out Layer:
  lines w0.25: 27.877,21.59 ccw(c29.147,21.59) 29.147,20.32 75.107,20.32 ccw(c75.107,21.59) 76.377,21.59 76.377,23.32 76.377,58.32 76.377,61.55 ccw(c75.107,61.55) 75.107,62.82 31.377,62.82 29.147,62.82 ccw(c29.147,61.55) 27.877,61.55 27.877,23.82 27.877,21.59

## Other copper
Top Layer:
  pour cut-out: 64.377,34.32 64.377,28.57 72.877,28.57 72.877,34.32
  pour cut-out: 38.877,38.57 38.877,40.82 45.627,40.82 45.627,38.57
  pour cut-out: 27.877,41.32 32.697,41.32 32.697,38.82 45.627,38.82 45.627,23.32 28.127,23.32
  pour cut-out: 43.858,62.838 43.858,55.57 54.108,55.57 54.108,62.838
  pour cut-out: 43.225,48.906 42.063,48.906 42.063,47.828 43.218,47.828
GND:
  pour cut-out: 28.157,41.32 28.157,23.32 35.377,23.32 35.377,24.57 cw(c37.377,24.57) 37.377,26.57 cw(c37.377,24.82) 39.127,24.82 ccw(c40.627,24.82) 40.627,23.32 45.627,23.32 45.627,40.82 38.622,40.82 ccw(c38.122,40.82) 38.122,41.32
  pour cut-out: 43.877,62.82 43.877,55.32 54.127,55.32 54.127,62.82
Bottom Layer:
  pour cut-out: 28.157,41.32 45.627,41.32 45.627,23.32 39.837,23.32 cw(c39.837,23.546) 39.612,23.546 cw(c40.838,24.772) 39.104,24.772 39.104,25.298 38.052,26.35 ccw(c37.402,25.699) 37.402,26.619 ccw(c37.402,24.534) 35.928,26.009 35.776,25.857 ccw(c36.88,24.753) 35.319,24.753 35.319,23.32 28.157,23.32
  pour cut-out: 28.055,48.666 32.754,48.666 cw(c32.754,46.126) 35.294,46.126 35.294,44.78 39.383,40.691 39.383,39.878 28.055,39.878
  pour cut-out: 43.877,62.82 43.877,55.32 54.127,55.32 54.127,62.82

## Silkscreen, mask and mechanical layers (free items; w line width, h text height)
Top Overlay:
  lines w0.2: 29.167,60.706 29.167,61.806 30.342,61.806 ; 67.811,59.606 68.986,59.606 68.986,60.706
  text "USER" at 54.42,56.21 h1.2
  text "RST" at 60.977,40.12 h1.2
  text "BOOT" at 59.977,35.82 h1.2
  text "WIZMC-T1L" at 30.777,22.02 h1.2
  text "REV : 1.0" at 30.777,20.92 h1.2
Bottom Overlay:
  text "POWER" at 64.427,46.609 h1.2 r180
  text "V-Level" at 64.402,42.215 h1.2 r180
  text "LINK" at 64.376,37.835 h1.2 r180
